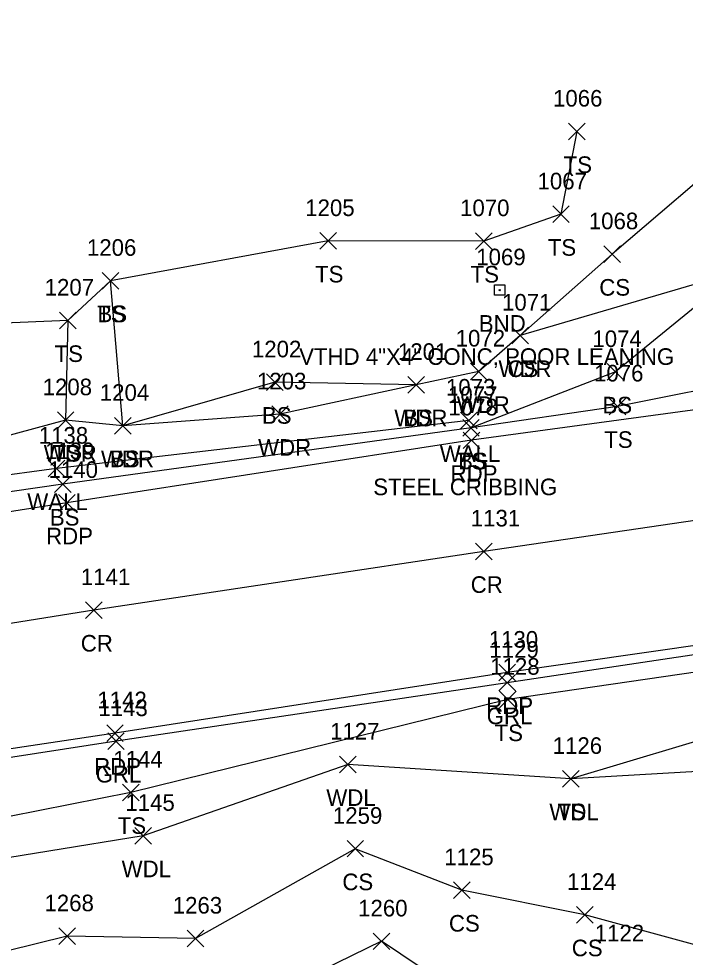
# Model space of a CAD drawing. Extents: x 1502119 to 1504100, y 606168 to 606406.
# Drawn here: x 1503856.3 to 1503936.5, y 606269.9 to 606383 of the extents above; entities that cross this region are included whole.
import ezdxf

# ---------------------------------------------------------------- set-up
doc = ezdxf.new("R2010")
doc.units = 0
for name, color, linetype in [('L_A', 7, 'Continuous'), ('L_C', 7, 'Continuous'), ('L_I', 7, 'Continuous'), ('L_TIC', 7, 'Continuous'), ('LAWA', 7, 'Continuous'), ('LELB', 7, 'Continuous'), ('Level 18', 7, 'Continuous'), ('LW', 7, 'Continuous'), ('M_A', 7, 'Continuous'), ('M_C', 7, 'Continuous'), ('M_I', 7, 'Continuous'), ('P_A', 7, 'Continuous'), ('P_I', 7, 'Continuous'), ('P_TIC', 7, 'Continuous'), ('PET', 7, 'Continuous'), ('PRC', 7, 'Continuous'), ('R_A', 7, 'Continuous'), ('R_I', 7, 'Continuous'), ('R_TIC', 7, 'Continuous'), ('RGR', 7, 'Continuous')]:
    doc.layers.add(name, color=color, linetype=linetype)

msp = doc.modelspace()

# ---------------------------------------------------------------- linework, layer by layer
at = {"layer": 'L_TIC'}
for points in [[(1503922.46, 606368.4), (1503924.46, 606370.4)], [(1503924.46, 606368.4), (1503922.46, 606370.4)], [(1503920.54, 606358.43), (1503922.54, 606360.43)], [(1503922.54, 606358.43), (1503920.54, 606360.43)], [(1503892.52, 606355.21), (1503894.52, 606357.21)], [(1503894.52, 606355.21), (1503892.52, 606357.21)], [(1503911.25, 606355.2), (1503913.25, 606357.2)], [(1503913.25, 606355.2), (1503911.25, 606357.2)], [(1503926.71, 606353.62), (1503928.71, 606355.62)], [(1503928.71, 606353.62), (1503926.71, 606355.62)], [(1503866.3, 606350.42), (1503868.3, 606352.42)], [(1503868.3, 606350.42), (1503866.3, 606352.42)], [(1503866.3, 606350.42), (1503868.3, 606352.42)], [(1503868.3, 606350.42), (1503866.3, 606352.42)], [(1503861.16, 606345.63), (1503863.16, 606347.63)], [(1503863.16, 606345.63), (1503861.16, 606347.63)], [(1503861.16, 606345.63), (1503863.16, 606347.63)], [(1503863.16, 606345.63), (1503861.16, 606347.63)], [(1503915.64, 606343.82), (1503917.64, 606345.82)], [(1503917.64, 606343.82), (1503915.64, 606345.82)], [(1503915.64, 606343.82), (1503917.64, 606345.82)], [(1503917.64, 606343.82), (1503915.64, 606345.82)], [(1503910.63, 606339.49), (1503912.63, 606341.49)], [(1503912.63, 606339.49), (1503910.63, 606341.49)], [(1503927.1, 606339.43), (1503929.1, 606341.43)], [(1503929.1, 606339.43), (1503927.1, 606341.43)], [(1503886.1, 606338.19), (1503888.1, 606340.19)], [(1503888.1, 606338.19), (1503886.1, 606340.19)], [(1503903.12, 606337.88), (1503905.12, 606339.88)], [(1503905.12, 606337.88), (1503903.12, 606339.88)], [(1503903.12, 606337.88), (1503905.12, 606339.88)], [(1503905.12, 606337.88), (1503903.12, 606339.88)], [(1503886.71, 606334.33), (1503888.71, 606336.33)], [(1503888.71, 606334.33), (1503886.71, 606336.33)], [(1503927.35, 606335.28), (1503929.35, 606337.28)], [(1503929.35, 606335.28), (1503927.35, 606337.28)], [(1503860.91, 606333.62), (1503862.91, 606335.62)], [(1503862.91, 606333.62), (1503860.91, 606335.62)], [(1503860.91, 606333.62), (1503862.91, 606335.62)], [(1503862.91, 606333.62), (1503860.91, 606335.62)], [(1503909.46, 606333.58), (1503911.46, 606335.58)], [(1503911.46, 606333.58), (1503909.46, 606335.58)], [(1503867.8, 606332.95), (1503869.8, 606334.95)], [(1503869.8, 606332.95), (1503867.8, 606334.95)], [(1503867.8, 606332.95), (1503869.8, 606334.95)], [(1503869.8, 606332.95), (1503867.8, 606334.95)], [(1503909.71, 606332.69), (1503911.71, 606334.69)], [(1503911.71, 606332.69), (1503909.71, 606334.69)], [(1503909.71, 606332.69), (1503911.71, 606334.69)], [(1503911.71, 606332.69), (1503909.71, 606334.69)], [(1503859.8, 606327.79), (1503861.8, 606329.79)], [(1503861.8, 606327.79), (1503859.8, 606329.79)], [(1503860.57, 606325.92), (1503862.57, 606327.92)], [(1503862.57, 606325.92), (1503860.57, 606327.92)], [(1503914.14, 606299.95), (1503916.14, 606301.95)], [(1503916.14, 606299.95), (1503914.14, 606301.95)], [(1503894.88, 606292.14), (1503896.88, 606294.14)], [(1503896.88, 606292.14), (1503894.88, 606294.14)], [(1503921.72, 606290.41), (1503923.72, 606292.41)], [(1503923.72, 606290.41), (1503921.72, 606292.41)], [(1503921.72, 606290.41), (1503923.72, 606292.41)], [(1503923.72, 606290.41), (1503921.72, 606292.41)], [(1503868.77, 606288.77), (1503870.77, 606290.77)], [(1503870.77, 606288.77), (1503868.77, 606290.77)], [(1503870.23, 606283.55), (1503872.23, 606285.55)], [(1503872.23, 606283.55), (1503870.23, 606285.55)], [(1503895.78, 606281.99), (1503897.78, 606283.99)], [(1503897.78, 606281.99), (1503895.78, 606283.99)], [(1503908.61, 606277), (1503910.61, 606279)], [(1503910.61, 606277), (1503908.61, 606279)], [(1503923.4, 606274.03), (1503925.4, 606276.03)], [(1503925.4, 606274.03), (1503923.4, 606276.03)], [(1503861.1, 606271.45), (1503863.1, 606273.45)], [(1503863.1, 606271.45), (1503861.1, 606273.45)], [(1503876.54, 606271.17), (1503878.54, 606273.17)], [(1503878.54, 606271.17), (1503876.54, 606273.17)], [(1503898.94, 606270.83), (1503900.94, 606272.83)], [(1503900.94, 606270.83), (1503898.94, 606272.83)]]:
    msp.add_lwpolyline(points, dxfattribs=at)
at = {"layer": 'LAWA'}
for points in [[(1503990.71, 606382.98), (1503966.9, 606374.16), (1503949.79, 606353.75), (1503942.92, 606352.55), (1503916.64, 606344.82), (1503911.63, 606340.49), (1503904.12, 606338.88), (1503887.71, 606335.33), (1503868.8, 606333.95), (1503861.91, 606334.62), (1503846, 606330.34), (1503828.45, 606328.53), (1503809.6, 606325.61), (1503789.35, 606322.82), (1503764.11, 606318.67), (1503746.35, 606317.25), (1503727.35, 606312.95), (1503709.14, 606312.53), (1503674.87, 606310.32), (1503655.25, 606308.46), (1503623.87, 606310.46), (1503602.45, 606314.46)], [(1503949.06, 606292.95), (1503922.72, 606291.41), (1503895.88, 606293.14), (1503871.23, 606284.55), (1503848.49, 606280.84), (1503822.63, 606273.75), (1503793.16, 606269.59), (1503770.58, 606267.1), (1503744.52, 606264.72), (1503721.39, 606263.89), (1503714.66, 606265.31), (1503698.22, 606260.24), (1503685.38, 606258.11), (1503660.65, 606259.69), (1503652.68, 606259.1), (1503650.68, 606259.07), (1503643.68, 606257.82), (1503632.11, 606261.1), (1503598.78, 606263.09)]]:
    msp.add_lwpolyline(points, dxfattribs=at)
at = {"layer": 'LELB'}
for points in [[(1503923.46, 606369.4), (1503921.54, 606359.43), (1503912.25, 606356.2), (1503893.52, 606356.21), (1503867.3, 606351.42), (1503862.16, 606346.63), (1503844.87, 606345.92), (1503823.53, 606352.97), (1503809.18, 606352.42), (1503787.72, 606358.18), (1503768.27, 606361.44), (1503750.54, 606364.68), (1503739.07, 606351.46), (1503723.82, 606341.62), (1503705.03, 606342.87), (1503687.78, 606335.89), (1503674.36, 606336.73), (1503654.48, 606335.34), (1503625.89, 606329.25), (1503604.28, 606329.18)], [(1504054.79, 606370.18), (1503996.69, 606358.67), (1503972.76, 606361.65), (1503963.87, 606349.96), (1503956.53, 606341.41), (1503954.72, 606340.41), (1503948.8, 606340.02), (1503945.63, 606339.72), (1503928.35, 606336.28), (1503910.71, 606333.69)], [(1503943.4, 606368.02), (1503927.71, 606354.62), (1503916.64, 606344.82)], [(1503942.92, 606352.55), (1503928.1, 606340.43), (1503910.71, 606333.69), (1503861.57, 606326.92), (1503811.33, 606319.63), (1503759.93, 606312.02), (1503711.14, 606306.21), (1503662.13, 606303.9), (1503623.99, 606305.38), (1503602.03, 606307.61), (1503601.52, 606307.57), (1503602.45, 606314.46)], [(1503904.12, 606338.88), (1503887.1, 606339.19), (1503868.8, 606333.95), (1503867.3, 606351.42)], [(1503862.16, 606346.63), (1503861.91, 606334.62)], [(1504084.2, 606316.18), (1504049.45, 606313.99), (1504016.18, 606312.8), (1504000.76, 606312.78), (1503990.22, 606311.65), (1503980.1, 606310.35), (1503956.75, 606307.04), (1503915.14, 606300.95), (1503869.77, 606289.77), (1503847.82, 606285.43), (1503820.78, 606281.87), (1503792.45, 606279.04), (1503767.54, 606276.84), (1503743.42, 606274.71), (1503718.48, 606272.4), (1503713.68, 606272.36), (1503654.98, 606271.32), (1503649.47, 606271.35), (1503622.06, 606272.76), (1503601.12, 606274.82)], [(1504016.73, 606298.23), (1504003.23, 606304.17), (1503993.35, 606301.91), (1503983, 606300.37), (1503956.25, 606301.46), (1503922.72, 606291.41)], [(1503984.83, 606255.06), (1503973.29, 606256.69), (1503955.93, 606260.62), (1503952.28, 606267.45), (1503924.4, 606275.03), (1503909.61, 606278), (1503896.78, 606282.99), (1503877.54, 606272.17), (1503862.1, 606272.45), (1503836.9, 606266.22), (1503825.65, 606259.98), (1503818.28, 606261.16), (1503806.2, 606257.22), (1503801.33, 606241.79), (1503784.67, 606238.5), (1503757.1, 606237.25), (1503731.6, 606237.76), (1503710.27, 606237.78), (1503692.02, 606229.45), (1503676.15, 606227.07), (1503663.08, 606221.89), (1503653.08, 606223.12)], [(1503952.28, 606267.45), (1503927.72, 606268.82), (1503911.45, 606264.08), (1503899.94, 606271.83), (1503881.96, 606263.04), (1503860.02, 606261.89), (1503842.33, 606253.64), (1503837.4, 606251.84), (1503840.87, 606237.08)]]:
    msp.add_lwpolyline(points, dxfattribs=at)
at = {"layer": 'Level 18'}
msp.add_lwpolyline([(1503913.54, 606350.91), (1503914.79, 606350.91), (1503914.79, 606349.66), (1503913.54, 606349.66)], close=True, dxfattribs=at)
msp.add_circle((1503914.16, 606350.28), 0.0833, dxfattribs=at)
at = {"layer": 'LW'}
msp.add_lwpolyline([(1503910.46, 606334.58), (1503860.8, 606328.79), (1503810.94, 606322.05), (1503761.44, 606314.27), (1503711.84, 606307.81), (1503661.97, 606305.03), (1503624.1, 606306.33), (1503602.1, 606309.62), (1503602.45, 606314.46)], dxfattribs=at)
at = {"layer": 'P_TIC'}
for points in [[(1503909.76, 606331.19), (1503911.76, 606333.19)], [(1503911.76, 606331.19), (1503909.76, 606333.19)], [(1503861.06, 606323.66), (1503863.06, 606325.66)], [(1503863.06, 606323.66), (1503861.06, 606325.66)], [(1503911.24, 606317.81), (1503913.24, 606319.81)], [(1503913.24, 606317.81), (1503911.24, 606319.81)], [(1503864.3, 606310.74), (1503866.3, 606312.74)], [(1503866.3, 606310.74), (1503864.3, 606312.74)], [(1503914.05, 606303.21), (1503916.05, 606305.21)], [(1503916.05, 606303.21), (1503914.05, 606305.21)], [(1503866.85, 606295.91), (1503868.85, 606297.91)], [(1503868.85, 606295.91), (1503866.85, 606297.91)]]:
    msp.add_lwpolyline(points, dxfattribs=at)
at = {"layer": 'PET'}
for points in [[(1504085.41, 606349.16), (1504052.4, 606348.69), (1503999.05, 606344.18), (1503952.76, 606337.92), (1503910.76, 606332.19), (1503862.06, 606324.66), (1503811.74, 606316.76), (1503760.3, 606309.68), (1503710.83, 606303.94), (1503662.2, 606301.66), (1503623.65, 606303.36), (1503601.52, 606305.18)], [(1504084.52, 606320.63), (1504050.65, 606320.45), (1504000.43, 606315.8), (1503956.16, 606310.12), (1503915.05, 606304.21), (1503867.85, 606296.91), (1503814.4, 606288.86), (1503766.38, 606281.21), (1503714.75, 606276.43), (1503655.34, 606274.1), (1503622.19, 606275.72), (1503601.58, 606277.52)]]:
    msp.add_lwpolyline(points, dxfattribs=at)
at = {"layer": 'PRC'}
msp.add_lwpolyline([(1504085.68, 606335.47), (1504051.53, 606335.36), (1503999.5, 606331.04), (1503953.49, 606324.86), (1503912.24, 606318.81), (1503865.3, 606311.74), (1503812.8, 606303.34), (1503763.88, 606296.53), (1503711.85, 606290.88), (1503656.36, 606289.42), (1503622.63, 606290.92), (1503602.08, 606292.63)], dxfattribs=at)
at = {"layer": 'R_TIC'}
for points in [[(1503914.05, 606301.99), (1503916.05, 606303.99)], [(1503916.05, 606301.99), (1503914.05, 606303.99)], [(1503866.97, 606294.96), (1503868.97, 606296.96)], [(1503868.97, 606294.96), (1503866.97, 606296.96)]]:
    msp.add_lwpolyline(points, dxfattribs=at)
at = {"layer": 'RGR'}
msp.add_lwpolyline([(1504084.44, 606319.87), (1504050.55, 606319.53), (1504000.64, 606315), (1503956.05, 606309.11), (1503915.05, 606302.99), (1503867.97, 606295.96), (1503814.82, 606287.72), (1503766.2, 606280.53), (1503714.79, 606275.76), (1503655.19, 606273.62), (1503622.1, 606275.05), (1503601.6, 606277)], dxfattribs=at)

# ---------------------------------------------------------------- texts
at = {"layer": 'L_A'}
for s, p in [('TS', (1503921.86, 606364.4)), ('TS', (1503919.95, 606354.43)), ('TS', (1503891.93, 606351.21)), ('TS', (1503910.66, 606351.2)), ('CS', (1503926.15, 606349.62)), ('TS', (1503865.71, 606346.42)), ('BS', (1503865.74, 606346.42)), ('TS', (1503860.57, 606341.63)), ('TS', (1503860.57, 606341.63)), ('WDR', (1503914.01, 606339.82)), ('CS', (1503915.09, 606339.82)), ('WDR', (1503908.99, 606335.49)), ('BS', (1503926.54, 606335.43)), ('BS', (1503885.54, 606334.19)), ('WDR', (1503901.48, 606333.88)), ('BS', (1503902.56, 606333.88)), ('TS', (1503926.75, 606331.28)), ('WDR', (1503885.08, 606330.33)), ('WDR', (1503859.27, 606329.62)), ('TS', (1503860.32, 606329.62)), ('WDR', (1503866.16, 606328.95)), ('BS', (1503867.24, 606328.95)), ('WALL', (1503906.95, 606329.58)), ('TS', (1503909.12, 606328.69)), ('BS', (1503909.15, 606328.69)), ('WALL', (1503857.29, 606323.79)), ('BS', (1503860.01, 606321.92)), ('TS', (1503913.55, 606295.95)), ('WDL', (1503893.29, 606288.14)), ('WDL', (1503920.14, 606286.41)), ('TS', (1503921.13, 606286.41)), ('TS', (1503868.18, 606284.77)), ('WDL', (1503868.65, 606279.55)), ('CS', (1503895.22, 606277.99)), ('CS', (1503908.05, 606273)), ('CS', (1503922.84, 606270.03))]:
    msp.add_text(s, height=2, dxfattribs=at).set_placement(p)
at = {"layer": 'L_C'}
msp.add_text('STEEL CRIBBING', height=2, dxfattribs=at).set_placement((1503898.94, 606325.58))
at = {"layer": 'L_I'}
for s, p in [('1066', (1503920.58, 606372.4)), ('1067', (1503918.72, 606362.43)), ('1205', (1503890.75, 606359.21)), ('1070', (1503909.39, 606359.2)), ('1068', (1503924.89, 606357.62)), ('1206', (1503864.47, 606354.42)), ('1206', (1503864.47, 606354.42)), ('1207', (1503859.38, 606349.63)), ('1207', (1503859.38, 606349.63)), ('1071', (1503914.44, 606347.82)), ('1071', (1503914.44, 606347.82)), ('1072', (1503908.86, 606343.49)), ('1074', (1503925.32, 606343.43)), ('1202', (1503884.33, 606342.19)), ('1201', (1503901.91, 606341.88)), ('1201', (1503901.91, 606341.88)), ('1076', (1503925.52, 606339.28)), ('1203', (1503884.94, 606338.33)), ('1208', (1503859.14, 606337.62)), ('1208', (1503859.14, 606337.62)), ('1204', (1503866.02, 606336.95)), ('1204', (1503866.02, 606336.95)), ('1073', (1503907.69, 606337.58)), ('1077', (1503907.94, 606336.69)), ('1077', (1503907.94, 606336.69)), ('1138', (1503858.67, 606331.79)), ('1139', (1503859.43, 606329.92)), ('1128', (1503913.02, 606303.95)), ('1127', (1503893.75, 606296.14)), ('1126', (1503920.54, 606294.41)), ('1126', (1503920.54, 606294.41)), ('1144', (1503867.64, 606292.77)), ('1145', (1503869.1, 606287.55)), ('1259', (1503894.08, 606285.99)), ('1125', (1503907.49, 606281)), ('1124', (1503922.27, 606278.03)), ('1268', (1503859.36, 606275.45)), ('1263', (1503874.8, 606275.17)), ('1260', (1503897.12, 606274.83)), ('1122', (1503925.6, 606271.82))]:
    msp.add_text(s, height=2, dxfattribs=at).set_placement(p)
at = {"layer": 'M_A'}
msp.add_text('BND', height=2, dxfattribs=at).set_placement((1503911.65, 606345.28))
at = {"layer": 'M_C'}
msp.add_text('VTHD 4"X4" CONC, POOR LEANING', height=2, dxfattribs=at).set_placement((1503890.02, 606341.28))
at = {"layer": 'M_I'}
msp.add_text('1069', height=2, dxfattribs=at).set_placement((1503911.34, 606353.28))
at = {"layer": 'P_A'}
for s, p in [('RDP', (1503908.25, 606327.19)), ('RDP', (1503859.55, 606319.66)), ('CR', (1503910.67, 606313.81)), ('CR', (1503863.73, 606306.74)), ('RDP', (1503912.54, 606299.21)), ('RDP', (1503865.34, 606291.91))]:
    msp.add_text(s, height=2, dxfattribs=at).set_placement(p)
at = {"layer": 'P_I'}
for s, p in [('1078', (1503907.99, 606335.19)), ('1140', (1503859.85, 606327.66)), ('1131', (1503910.68, 606321.81)), ('1141', (1503863.74, 606314.74)), ('1130', (1503912.84, 606307.21)), ('1142', (1503865.72, 606299.91))]:
    msp.add_text(s, height=2, dxfattribs=at).set_placement(p)
at = {"layer": 'R_A'}
for p in [(1503912.6, 606297.99), (1503865.52, 606290.96)]:
    msp.add_text('GRL', height=2, dxfattribs=at).set_placement(p)
at = {"layer": 'R_I'}
for s, p in [('1129', (1503912.92, 606305.99)), ('1143', (1503865.85, 606298.96))]:
    msp.add_text(s, height=2, dxfattribs=at).set_placement(p)

doc.saveas('drawing.dxf')
